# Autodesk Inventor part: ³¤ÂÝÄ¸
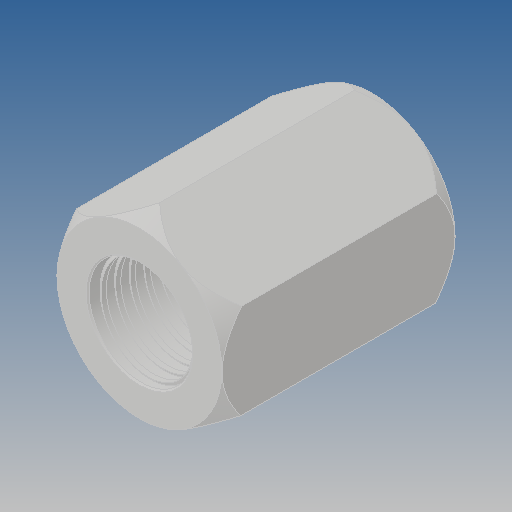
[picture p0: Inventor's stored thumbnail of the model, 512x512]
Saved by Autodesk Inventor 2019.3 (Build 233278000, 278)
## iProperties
Created: 2017-08
Part Number: ³¤ÂÝÄ¸
Material: Ogólny
Document SubType Name: Modeling
Designer: Admin
Density: 1 g/cm^3
Appearance: Domyślna
Author: Admin
Revision Number: ÈÎºÎ
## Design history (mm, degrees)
feature "ÊäÈë1"
node "Bryła1"
